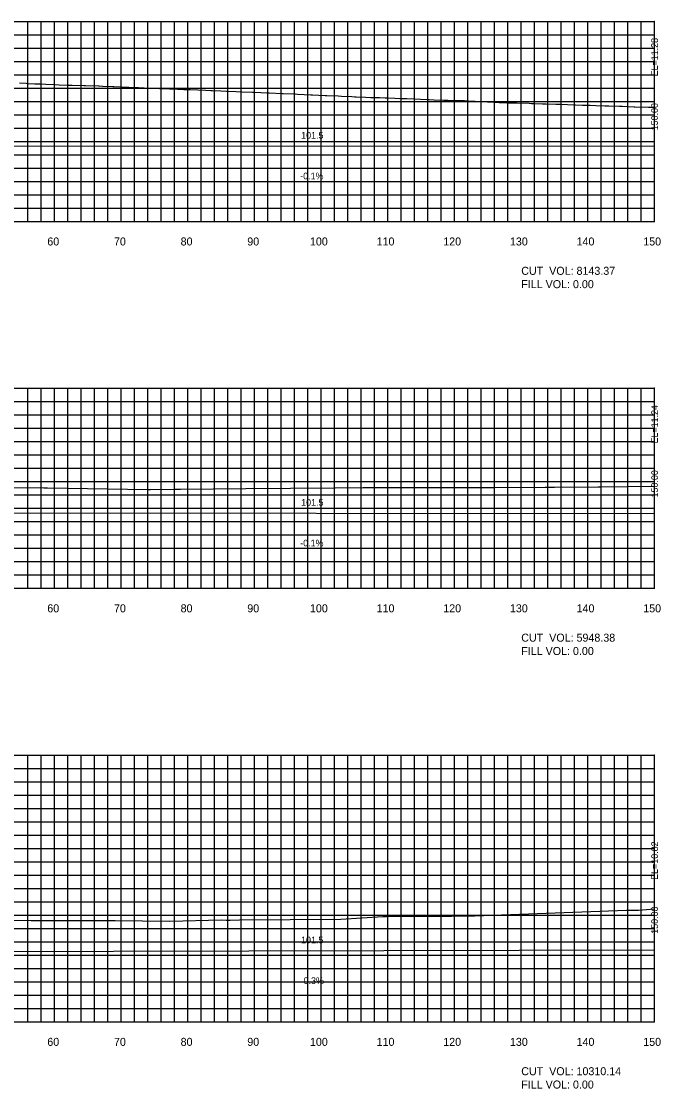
# Model space of a CAD drawing. Extents: x 1797789 to 1803805, y 249066 to 250293.
# Drawn here: x 1803026 to 1803121.9, y 250089.4 to 250249.4 of the extents above; entities that cross this region are included whole.
import ezdxf

# ---------------------------------------------------------------- set-up
doc = ezdxf.new("R2010")
doc.units = 0
for name, color, linetype in [('10', 7, 'Continuous'), ('3', 7, 'Continuous'), ('4', 7, 'Continuous'), ('60', 7, 'Continuous'), ('ANNO-TXT', 7, 'Continuous'), ('CL-CNST', 7, 'Continuous'), ('Level 62', 7, 'Continuous'), ('M-ROADS', 7, 'Continuous')]:
    doc.layers.add(name, color=color, linetype=linetype)

msp = doc.modelspace()

# ---------------------------------------------------------------- linework, layer by layer
for p, q in [((1803121, 250230.71), (1803121, 250232.71)), ((1803121, 250175.67), (1803121, 250177.67)), ((1803121, 250110.25), (1803121, 250112.25))]:
    msp.add_line(p, q)
at = {"layer": '60'}
for p, q in [((1803121, 250219.43), (1803121, 250249.43)), ((1803121.06, 250249.43), (1803121, 250249.43)), ((1803121.06, 250239.43), (1803121, 250239.43)), ((1803121.06, 250229.43), (1803121, 250229.43)), ((1802821, 250219.43), (1803121, 250219.43)), ((1803031, 250219.37), (1803031, 250219.43)), ((1803041, 250219.37), (1803041, 250219.43)), ((1803051, 250219.37), (1803051, 250219.43)), ((1803061, 250219.37), (1803061, 250219.43)), ((1803071, 250219.37), (1803071, 250219.43)), ((1803081, 250219.37), (1803081, 250219.43)), ((1803091, 250219.37), (1803091, 250219.43)), ((1803101, 250219.37), (1803101, 250219.43)), ((1803111, 250219.37), (1803111, 250219.43)), ((1803121, 250219.37), (1803121, 250219.43)), ((1803121.06, 250219.43), (1803121, 250219.43)), ((1803121, 250164.43), (1803121, 250194.43)), ((1803121.06, 250194.43), (1803121, 250194.43)), ((1803121.06, 250184.43), (1803121, 250184.43)), ((1803121.06, 250174.43), (1803121, 250174.43)), ((1802821, 250164.43), (1803121, 250164.43)), ((1803031, 250164.37), (1803031, 250164.43)), ((1803041, 250164.37), (1803041, 250164.43)), ((1803051, 250164.37), (1803051, 250164.43)), ((1803061, 250164.37), (1803061, 250164.43)), ((1803071, 250164.37), (1803071, 250164.43)), ((1803081, 250164.37), (1803081, 250164.43)), ((1803091, 250164.37), (1803091, 250164.43)), ((1803101, 250164.37), (1803101, 250164.43)), ((1803111, 250164.37), (1803111, 250164.43)), ((1803121, 250164.37), (1803121, 250164.43)), ((1803121.06, 250164.43), (1803121, 250164.43)), ((1803121, 250099.43), (1803121, 250139.43)), ((1803121.06, 250139.43), (1803121, 250139.43)), ((1803121.06, 250129.43), (1803121, 250129.43)), ((1803121.06, 250119.43), (1803121, 250119.43)), ((1803121.06, 250109.43), (1803121, 250109.43)), ((1802821, 250099.43), (1803121, 250099.43)), ((1803031, 250099.37), (1803031, 250099.43)), ((1803041, 250099.37), (1803041, 250099.43)), ((1803051, 250099.37), (1803051, 250099.43)), ((1803061, 250099.37), (1803061, 250099.43)), ((1803071, 250099.37), (1803071, 250099.43)), ((1803081, 250099.37), (1803081, 250099.43)), ((1803091, 250099.37), (1803091, 250099.43)), ((1803101, 250099.37), (1803101, 250099.43)), ((1803111, 250099.37), (1803111, 250099.43)), ((1803121, 250099.37), (1803121, 250099.43)), ((1803121.06, 250099.43), (1803121, 250099.43))]:
    msp.add_line(p, q, dxfattribs=at)
at = {"layer": 'CL-CNST'}
for points in [[(1802821, 250232.81), (1802922.5, 250230.78), (1802923.5, 250230.74), (1802930.5, 250230.64), (1802930.5, 250230.64), (1802930.83, 250230.64), (1802931, 250230.14), (1802933, 250230.3), (1802937, 250230.38), (1802971, 250231.13), (1803005, 250230.38), (1803009, 250230.3), (1803011, 250230.14), (1803011.17, 250230.64), (1803011.5, 250230.64), (1803011.5, 250230.64), (1803018.5, 250230.74), (1803019.5, 250230.78), (1803121, 250230.71)], [(1802821, 250179.1), (1802922.5, 250175.74), (1802923.5, 250175.7), (1802930.5, 250175.59), (1802930.5, 250175.59), (1802930.83, 250175.59), (1802931, 250175.09), (1802933, 250175.25), (1802937, 250175.34), (1802971, 250176.09), (1803005, 250175.34), (1803009, 250175.25), (1803011, 250175.09), (1803011.17, 250175.59), (1803011.5, 250175.59), (1803011.5, 250175.59), (1803018.5, 250175.7), (1803019.5, 250175.74), (1803121, 250175.67)], [(1802821, 250113.38), (1802922.5, 250109.96), (1802923.5, 250109.92), (1802930.5, 250109.81), (1802930.5, 250109.81), (1802930.83, 250109.81), (1802931, 250109.31), (1802933, 250109.47), (1802937, 250109.56), (1802971, 250110.31), (1803005, 250109.56), (1803009, 250109.47), (1803011, 250109.31), (1803011.17, 250109.81), (1803011.5, 250109.81), (1803011.5, 250109.81), (1803018.5, 250109.92), (1803019.5, 250109.96), (1803121, 250110.25)]]:
    msp.add_lwpolyline(points, dxfattribs=at)
at = {"layer": 'Level 62'}
for p, q in [((1802821, 250249.43), (1803121, 250249.43)), ((1803027, 250219.43), (1803027, 250249.43)), ((1803029, 250219.43), (1803029, 250249.43)), ((1803031, 250219.43), (1803031, 250249.43)), ((1803033, 250219.43), (1803033, 250249.43)), ((1803035, 250219.43), (1803035, 250249.43)), ((1803037, 250219.43), (1803037, 250249.43)), ((1803039, 250219.43), (1803039, 250249.43)), ((1803041, 250219.43), (1803041, 250249.43)), ((1803043, 250219.43), (1803043, 250249.43)), ((1803045, 250219.43), (1803045, 250249.43)), ((1803047, 250219.43), (1803047, 250249.43)), ((1803049, 250219.43), (1803049, 250249.43)), ((1803051, 250219.43), (1803051, 250249.43)), ((1803053, 250219.43), (1803053, 250249.43)), ((1803055, 250219.43), (1803055, 250249.43)), ((1803057, 250219.43), (1803057, 250249.43)), ((1803059, 250219.43), (1803059, 250249.43)), ((1803061, 250219.43), (1803061, 250249.43)), ((1803063, 250219.43), (1803063, 250249.43)), ((1803065, 250219.43), (1803065, 250249.43)), ((1803067, 250219.43), (1803067, 250249.43)), ((1803069, 250219.43), (1803069, 250249.43)), ((1803071, 250219.43), (1803071, 250249.43)), ((1803073, 250219.43), (1803073, 250249.43)), ((1803075, 250219.43), (1803075, 250249.43)), ((1803077, 250219.43), (1803077, 250249.43)), ((1803079, 250219.43), (1803079, 250249.43)), ((1803081, 250219.43), (1803081, 250249.43)), ((1803083, 250219.43), (1803083, 250249.43)), ((1803085, 250219.43), (1803085, 250249.43)), ((1803087, 250219.43), (1803087, 250249.43)), ((1803089, 250219.43), (1803089, 250249.43)), ((1803091, 250219.43), (1803091, 250249.43)), ((1803093, 250219.43), (1803093, 250249.43)), ((1803095, 250219.43), (1803095, 250249.43)), ((1803097, 250219.43), (1803097, 250249.43)), ((1803099, 250219.43), (1803099, 250249.43)), ((1803101, 250219.43), (1803101, 250249.43)), ((1803103, 250219.43), (1803103, 250249.43)), ((1803105, 250219.43), (1803105, 250249.43)), ((1803107, 250219.43), (1803107, 250249.43)), ((1803109, 250219.43), (1803109, 250249.43)), ((1803111, 250219.43), (1803111, 250249.43)), ((1803113, 250219.43), (1803113, 250249.43)), ((1803115, 250219.43), (1803115, 250249.43)), ((1803117, 250219.43), (1803117, 250249.43)), ((1803119, 250219.43), (1803119, 250249.43)), ((1803121, 250219.43), (1803121, 250249.43)), ((1802821, 250247.43), (1803121, 250247.43)), ((1802821, 250245.43), (1803121, 250245.43)), ((1802821, 250243.43), (1803121, 250243.43)), ((1802821, 250241.43), (1803121, 250241.43)), ((1802821, 250239.43), (1803121, 250239.43)), ((1802821, 250237.43), (1803121, 250237.43)), ((1802821, 250235.43), (1803121, 250235.43)), ((1802821, 250233.43), (1803121, 250233.43)), ((1802821, 250231.43), (1803121, 250231.43)), ((1802821, 250229.43), (1803121, 250229.43)), ((1802821, 250227.43), (1803121, 250227.43)), ((1802821, 250225.43), (1803121, 250225.43)), ((1802821, 250223.43), (1803121, 250223.43)), ((1802821, 250221.43), (1803121, 250221.43)), ((1802821, 250219.43), (1803121, 250219.43)), ((1802821, 250194.43), (1803121, 250194.43)), ((1803027, 250164.43), (1803027, 250194.43)), ((1803029, 250164.43), (1803029, 250194.43)), ((1803031, 250164.43), (1803031, 250194.43)), ((1803033, 250164.43), (1803033, 250194.43)), ((1803035, 250164.43), (1803035, 250194.43)), ((1803037, 250164.43), (1803037, 250194.43)), ((1803039, 250164.43), (1803039, 250194.43)), ((1803041, 250164.43), (1803041, 250194.43)), ((1803043, 250164.43), (1803043, 250194.43)), ((1803045, 250164.43), (1803045, 250194.43)), ((1803047, 250164.43), (1803047, 250194.43)), ((1803049, 250164.43), (1803049, 250194.43)), ((1803051, 250164.43), (1803051, 250194.43)), ((1803053, 250164.43), (1803053, 250194.43)), ((1803055, 250164.43), (1803055, 250194.43)), ((1803057, 250164.43), (1803057, 250194.43)), ((1803059, 250164.43), (1803059, 250194.43)), ((1803061, 250164.43), (1803061, 250194.43)), ((1803063, 250164.43), (1803063, 250194.43)), ((1803065, 250164.43), (1803065, 250194.43)), ((1803067, 250164.43), (1803067, 250194.43)), ((1803069, 250164.43), (1803069, 250194.43)), ((1803071, 250164.43), (1803071, 250194.43)), ((1803073, 250164.43), (1803073, 250194.43)), ((1803075, 250164.43), (1803075, 250194.43)), ((1803077, 250164.43), (1803077, 250194.43)), ((1803079, 250164.43), (1803079, 250194.43)), ((1803081, 250164.43), (1803081, 250194.43)), ((1803083, 250164.43), (1803083, 250194.43)), ((1803085, 250164.43), (1803085, 250194.43)), ((1803087, 250164.43), (1803087, 250194.43)), ((1803089, 250164.43), (1803089, 250194.43)), ((1803091, 250164.43), (1803091, 250194.43)), ((1803093, 250164.43), (1803093, 250194.43)), ((1803095, 250164.43), (1803095, 250194.43)), ((1803097, 250164.43), (1803097, 250194.43)), ((1803099, 250164.43), (1803099, 250194.43)), ((1803101, 250164.43), (1803101, 250194.43)), ((1803103, 250164.43), (1803103, 250194.43)), ((1803105, 250164.43), (1803105, 250194.43)), ((1803107, 250164.43), (1803107, 250194.43)), ((1803109, 250164.43), (1803109, 250194.43)), ((1803111, 250164.43), (1803111, 250194.43)), ((1803113, 250164.43), (1803113, 250194.43)), ((1803115, 250164.43), (1803115, 250194.43)), ((1803117, 250164.43), (1803117, 250194.43)), ((1803119, 250164.43), (1803119, 250194.43)), ((1803121, 250164.43), (1803121, 250194.43)), ((1802821, 250192.43), (1803121, 250192.43)), ((1802821, 250190.43), (1803121, 250190.43)), ((1802821, 250188.43), (1803121, 250188.43)), ((1802821, 250186.43), (1803121, 250186.43)), ((1802821, 250184.43), (1803121, 250184.43)), ((1802821, 250182.43), (1803121, 250182.43)), ((1802821, 250180.43), (1803121, 250180.43)), ((1802821, 250178.43), (1803121, 250178.43)), ((1802821, 250176.43), (1803121, 250176.43)), ((1802821, 250174.43), (1803121, 250174.43)), ((1802821, 250172.43), (1803121, 250172.43)), ((1802821, 250170.43), (1803121, 250170.43)), ((1802821, 250168.43), (1803121, 250168.43)), ((1802821, 250166.43), (1803121, 250166.43)), ((1802821, 250164.43), (1803121, 250164.43)), ((1802821, 250139.43), (1803121, 250139.43)), ((1803027, 250099.43), (1803027, 250139.43)), ((1803029, 250099.43), (1803029, 250139.43)), ((1803031, 250099.43), (1803031, 250139.43)), ((1803033, 250099.43), (1803033, 250139.43)), ((1803035, 250099.43), (1803035, 250139.43)), ((1803037, 250099.43), (1803037, 250139.43)), ((1803039, 250099.43), (1803039, 250139.43)), ((1803041, 250099.43), (1803041, 250139.43)), ((1803043, 250099.43), (1803043, 250139.43)), ((1803045, 250099.43), (1803045, 250139.43)), ((1803047, 250099.43), (1803047, 250139.43)), ((1803049, 250099.43), (1803049, 250139.43)), ((1803051, 250099.43), (1803051, 250139.43)), ((1803053, 250099.43), (1803053, 250139.43)), ((1803055, 250099.43), (1803055, 250139.43)), ((1803057, 250099.43), (1803057, 250139.43)), ((1803059, 250099.43), (1803059, 250139.43)), ((1803061, 250099.43), (1803061, 250139.43)), ((1803063, 250099.43), (1803063, 250139.43)), ((1803065, 250099.43), (1803065, 250139.43)), ((1803067, 250099.43), (1803067, 250139.43)), ((1803069, 250099.43), (1803069, 250139.43)), ((1803071, 250099.43), (1803071, 250139.43)), ((1803073, 250099.43), (1803073, 250139.43)), ((1803075, 250099.43), (1803075, 250139.43)), ((1803077, 250099.43), (1803077, 250139.43)), ((1803079, 250099.43), (1803079, 250139.43)), ((1803081, 250099.43), (1803081, 250139.43)), ((1803083, 250099.43), (1803083, 250139.43)), ((1803085, 250099.43), (1803085, 250139.43)), ((1803087, 250099.43), (1803087, 250139.43)), ((1803089, 250099.43), (1803089, 250139.43)), ((1803091, 250099.43), (1803091, 250139.43)), ((1803093, 250099.43), (1803093, 250139.43)), ((1803095, 250099.43), (1803095, 250139.43)), ((1803097, 250099.43), (1803097, 250139.43)), ((1803099, 250099.43), (1803099, 250139.43)), ((1803101, 250099.43), (1803101, 250139.43)), ((1803103, 250099.43), (1803103, 250139.43)), ((1803105, 250099.43), (1803105, 250139.43)), ((1803107, 250099.43), (1803107, 250139.43)), ((1803109, 250099.43), (1803109, 250139.43)), ((1803111, 250099.43), (1803111, 250139.43)), ((1803113, 250099.43), (1803113, 250139.43)), ((1803115, 250099.43), (1803115, 250139.43)), ((1803117, 250099.43), (1803117, 250139.43)), ((1803119, 250099.43), (1803119, 250139.43)), ((1803121, 250099.43), (1803121, 250139.43)), ((1802821, 250137.43), (1803121, 250137.43)), ((1802821, 250135.43), (1803121, 250135.43)), ((1802821, 250133.43), (1803121, 250133.43)), ((1802821, 250131.43), (1803121, 250131.43)), ((1802821, 250129.43), (1803121, 250129.43)), ((1802821, 250127.43), (1803121, 250127.43)), ((1802821, 250125.43), (1803121, 250125.43)), ((1802821, 250123.43), (1803121, 250123.43)), ((1802821, 250121.43), (1803121, 250121.43)), ((1802821, 250119.43), (1803121, 250119.43)), ((1802821, 250117.43), (1803121, 250117.43)), ((1802821, 250115.43), (1803121, 250115.43)), ((1802821, 250113.43), (1803121, 250113.43)), ((1802821, 250111.43), (1803121, 250111.43)), ((1802821, 250109.43), (1803121, 250109.43)), ((1802821, 250107.43), (1803121, 250107.43)), ((1802821, 250105.43), (1803121, 250105.43)), ((1802821, 250103.43), (1803121, 250103.43)), ((1802821, 250101.43), (1803121, 250101.43)), ((1802821, 250099.43), (1803121, 250099.43))]:
    msp.add_line(p, q, dxfattribs=at)
at = {"layer": 'M-ROADS'}
for points in [[(1803025.73, 250240.2), (1803026.71, 250240.14), (1803027.02, 250240.13), (1803028.02, 250240.08), (1803028.88, 250240.05), (1803029.69, 250240.01), (1803031.05, 250239.96), (1803031.67, 250239.93), (1803032.86, 250239.88), (1803033.22, 250239.87), (1803033.64, 250239.85), (1803035.4, 250239.8), (1803035.61, 250239.79), (1803037.57, 250239.74), (1803037.68, 250239.74), (1803038.17, 250239.72), (1803038.21, 250239.72), (1803039.71, 250239.65), (1803039.86, 250239.65), (1803041.84, 250239.56), (1803042.15, 250239.55), (1803043.6, 250239.49), (1803043.97, 250239.47), (1803044.45, 250239.45), (1803046.11, 250239.4), (1803046.74, 250239.37), (1803048.24, 250239.32), (1803048.62, 250239.3), (1803049.43, 250239.27), (1803050.37, 250239.23), (1803051.33, 250239.19), (1803052.5, 250239.14), (1803053.63, 250239.09), (1803054.43, 250239.06), (1803054.63, 250239.05), (1803055.93, 250239), (1803056.77, 250238.96), (1803058.23, 250238.9), (1803058.9, 250238.88), (1803059.07, 250238.87), (1803060.68, 250238.8), (1803061.03, 250238.79), (1803062.84, 250238.72), (1803063.16, 250238.71), (1803065.14, 250238.62), (1803065.26, 250238.62), (1803065.29, 250238.62), (1803067.09, 250238.54), (1803067.41, 250238.52), (1803067.43, 250238.52), (1803069.45, 250238.43), (1803069.62, 250238.42), (1803069.68, 250238.42), (1803071.58, 250238.33), (1803071.82, 250238.32), (1803073.55, 250238.24), (1803074.02, 250238.21), (1803075.57, 250238.14), (1803076.04, 250238.11), (1803076.06, 250238.11), (1803076.21, 250238.11), (1803077.65, 250238.05), (1803078.4, 250238.03), (1803079.71, 250237.99), (1803080.6, 250237.96), (1803080.86, 250237.95), (1803082.03, 250237.91), (1803082.79, 250237.88), (1803083.82, 250237.84), (1803084.99, 250237.79), (1803085.87, 250237.75), (1803086.87, 250237.71), (1803087.18, 250237.7), (1803087.93, 250237.67), (1803089.37, 250237.63), (1803089.98, 250237.61), (1803091.57, 250237.56), (1803092.04, 250237.55), (1803092.48, 250237.54), (1803093.76, 250237.47), (1803094.09, 250237.46), (1803095.96, 250237.36), (1803096.14, 250237.35), (1803097.67, 250237.27), (1803098.15, 250237.25), (1803098.19, 250237.25), (1803098.84, 250237.23), (1803100.21, 250237.19), (1803100.35, 250237.19), (1803102.2, 250237.14), (1803102.54, 250237.13), (1803103.02, 250237.11), (1803104.19, 250237.08), (1803104.74, 250237.06), (1803106.19, 250237.02), (1803106.93, 250237), (1803107.92, 250236.97), (1803108.86, 250236.94), (1803109.13, 250236.93), (1803110.18, 250236.88), (1803111.33, 250236.85), (1803112.17, 250236.81), (1803113.52, 250236.77), (1803113.52, 250236.77), (1803114.16, 250236.75), (1803115.72, 250236.71), (1803116.16, 250236.7), (1803117.92, 250236.64), (1803118.04, 250236.64), (1803120.09, 250236.58), (1803120.11, 250236.58), (1803120.15, 250236.58), (1803120.49, 250236.57), (1803121, 250236.54)], [(1803023.27, 250179.52), (1803029.36, 250179.5), (1803029.93, 250179.51), (1803044.94, 250179.25), (1803045.31, 250179.24), (1803045.4, 250179.23), (1803049.06, 250179.27), (1803049.24, 250179.28), (1803049.88, 250179.3), (1803059.68, 250179.41), (1803073.1, 250179.49), (1803077.3, 250179.54), (1803077.61, 250179.56), (1803077.67, 250179.56), (1803079.88, 250179.56), (1803080.36, 250179.55), (1803094.8, 250179.54), (1803096.92, 250179.55), (1803104.59, 250179.57), (1803105.16, 250179.57), (1803105.98, 250179.57), (1803112.54, 250179.63), (1803112.59, 250179.63), (1803112.98, 250179.65), (1803121, 250179.74)], [(1803018.77, 250114.77), (1803027.5, 250114.63), (1803027.77, 250114.63), (1803027.98, 250114.63), (1803035.4, 250114.62), (1803035.89, 250114.62), (1803036.14, 250114.61), (1803039.74, 250114.62), (1803040.1, 250114.62), (1803048.28, 250114.52), (1803056.04, 250114.71), (1803056.72, 250114.69), (1803057.18, 250114.7), (1803057.34, 250114.7), (1803058.71, 250114.75), (1803073.93, 250114.84), (1803080.24, 250115.21), (1803080.56, 250115.22), (1803080.77, 250115.23), (1803090.05, 250115.27), (1803090.55, 250115.28), (1803093.95, 250115.31), (1803094.05, 250115.32), (1803116.79, 250116.15), (1803117.42, 250116.16), (1803117.81, 250116.17), (1803118.02, 250116.19), (1803118.03, 250116.18), (1803118.59, 250116.16), (1803121, 250116.36)]]:
    msp.add_lwpolyline(points, dxfattribs=at)

# ---------------------------------------------------------------- texts
at = {"layer": '10'}
for s, p in [('60', (1803029.9, 250215.83)), ('70', (1803039.9, 250215.83)), ('80', (1803049.9, 250215.83)), ('90', (1803059.9, 250215.83)), ('100', (1803069.3, 250215.83)), ('110', (1803079.3, 250215.83)), ('120', (1803089.3, 250215.83)), ('130', (1803099.3, 250215.83)), ('140', (1803109.3, 250215.83)), ('150', (1803119.3, 250215.83)), ('60', (1803029.9, 250160.83)), ('70', (1803039.9, 250160.83)), ('80', (1803049.9, 250160.83)), ('90', (1803059.9, 250160.83)), ('100', (1803069.3, 250160.83)), ('110', (1803079.3, 250160.83)), ('120', (1803089.3, 250160.83)), ('130', (1803099.3, 250160.83)), ('140', (1803109.3, 250160.83)), ('150', (1803119.3, 250160.83)), ('60', (1803029.9, 250095.83)), ('70', (1803039.9, 250095.83)), ('80', (1803049.9, 250095.83)), ('90', (1803059.9, 250095.83)), ('100', (1803069.3, 250095.83)), ('110', (1803079.3, 250095.83)), ('120', (1803089.3, 250095.83)), ('130', (1803099.3, 250095.83)), ('140', (1803109.3, 250095.83)), ('150', (1803119.3, 250095.83))]:
    msp.add_text(s, height=1.2, dxfattribs=at).set_placement(p)
at = {"layer": '3'}
for s, p in [('EL=11.28', (1803121.5, 250241.18)), ('150.00', (1803121.5, 250233.09)), ('EL=11.24', (1803121.5, 250186.14)), ('150.00', (1803121.5, 250178.05)), ('EL=10.82', (1803121.5, 250120.72)), ('150.00', (1803121.5, 250112.63))]:
    msp.add_text(s, height=1, rotation=90, dxfattribs=at).set_placement(p)
at = {"layer": '4'}
for s, rotation, p in [('101.5', 359.9601, (1803067.98, 250231.85)), ('-0.1%', 359.9601, (1803067.84, 250225.75)), ('101.5', 359.9629, (1803067.98, 250176.81)), ('-0.1%', 359.9629, (1803067.84, 250170.71)), ('101.5', 0.1643, (1803067.97, 250111.2)), ('0.3%', 0.1643, (1803068.35, 250105.1))]:
    msp.add_text(s, height=1, rotation=rotation, dxfattribs=at).set_placement(p)
at = {"layer": 'ANNO-TXT'}
for s, p in [('CUT  VOL: 8143.37', (1803101, 250211.43)), ('FILL VOL: 0.00', (1803101, 250209.43)), ('CUT  VOL: 5948.38', (1803101, 250156.43)), ('FILL VOL: 0.00', (1803101, 250154.43)), ('CUT  VOL: 10310.14', (1803101, 250091.43)), ('FILL VOL: 0.00', (1803101, 250089.43))]:
    msp.add_text(s, height=1.2, dxfattribs=at).set_placement(p)

doc.saveas('drawing.dxf')
